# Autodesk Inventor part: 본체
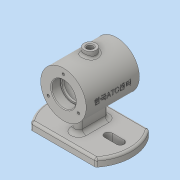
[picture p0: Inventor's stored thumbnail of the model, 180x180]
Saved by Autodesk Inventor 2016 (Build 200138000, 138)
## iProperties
Created: 2017-12
Part Number: 본체
Material: 일반
Document SubType Name: Modeling
Designer: 605-15
Density: 1 g/cm^3
Appearance: 기본값
Mass: 172.58 g
Surface Area: 486.488 cm^2
Volume: 172.58 cm^3
Author: 605-15
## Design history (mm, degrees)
sketch "스케치1"
  geometry: L1 (42.426, 35)-(-42.426, 35); L2 (42.426, -35)-(-42.426, -35); A1 r 55 centre (0, 0) between (-42.426, 35) and (-42.426, -35); A2 r 55 centre (0, 0) between (42.426, -35) and (42.426, 35); 1 further point
  constraints: 4 end point, 4 point on circle, 2 centre point, 2 horizontal, 1 coincident
  dimensions: "d1" = 70 distance between parallel lines of L2 L1; "d2" = 35 distance from line of point (0, 0) L1; "d64" = 55 radius of A2; "d65" = 55 radius of A1
extrude "돌출1" new body sketch "스케치1" distance "d3" = 10; taper "d4" = 0 deg
sketch "스케치2"
  geometry: L1 (0, 0)-(0, 62); C1 r 30 at (0, 62)
  constraints: 2 end point, 1 centre point, 1 coincident, 1 vertical
  dimensions: "d5" = 62 distance of L1.start L1.end; "d6" = 60 diameter of C1
extrude "돌출2" join sketch "스케치2" distance "d7" = 35; taper "d9" = 0 deg; dims "d8" = 35, "d10" = 0
sketch "스케치3"
  geometry: L1 (0, 15)-(0, -15); L2 (5, 15)-(5, -15); L3 (-5, -15)-(-5, 15); A1 r 5 centre (0, 15) between (5, 15) and (-5, 15); A2 r 5 centre (0, -15) between (-5, -15) and (5, -15); 1 further point
  constraints: 8 end point, 4 point on circle, 4 tangent, 2 centre point, 1 midpoint, 1 parallel, 1 vertical
  dimensions: "d11" = 5 radius of A2; "d12" = 30 distance of L1.start L1.end
extrude "돌출3" join sketch "스케치3" stored distance "d13" = 35; taper "d14" = 0 deg
node "작업 평면1"
sketch "스케치5"
  geometry: C1 r 8 at (0, 0); 1 further point
  constraints: 1 centre point, 1 coincident
  dimensions: "d24" = 16 diameter of C1
extrude "돌출4" join sketch "스케치5" distance "d25" = 37; taper "d26" = 0 deg
sketch "스케치4"
  geometry: L1 (62, 35)-(62, -35); L2 (32, -35)-(92, -35) reference; L3 (0, -35)-(0, 35) reference; L4 (92, 35)-(32, 35) reference; L5 (62, 35)-(78, 35); L6 (78, 35)-(78, 23); L7 (78, 23)-(76, 23); L8 (76, 23)-(76, 20); L9 (76, 20)-(87, 20); L10 (87, 20)-(87, -20); L11 (87, -20)-(76, -20); L12 (76, -20)-(76, -23); L13 (76, -23)-(78, -23); L14 (78, -23)-(78, -35); L15 (78, -35)-(62, -35); 1 further point
  constraints: 24 end point, 6 perpendicular, 6 point on line, 2 midpoint, 2 vertical, 1 collinear
  dimensions: "d15" = 62 distance between parallel lines of L3 L1; "d16" = 16 distance between parallel lines of L1 L6; "d17" = 14 distance between parallel lines of L1 L8; "d18" = 25 distance between parallel lines of L1 L10; "d19" = 12 distance of L5.end L6.end; "d20" = 40 distance of L9.end L10.end; "d21" = 12 distance of L13.end L14.end; "d22" = 3 distance of L7.end L8.end
revolve "회전1" sketch "스케치4" stored, may be unused: angle "d27" = 90 deg
fillet "모깎기1" dims "d28" = 3
fillet "모깎기2" dims "d29" = 0.3
chamfer "모따기1" distance "d30" = 1; stored, may be unused: second distance "d31" = 2, angle "d32" = 45 deg
sketch "스케치6"
  geometry: C1 r 4 at (0, 0); 1 further point
  constraints: 1 centre point, 1 coincident
  dimensions: "d33" = 8 diameter of C1
extrude "돌출5" cut sketch "스케치6" stored distance "d34" = 37; taper "d35" = 0 deg
chamfer "모따기2" distance "d36" = 1; stored, may be unused: second distance "d37" = 2, angle "d38" = 45 deg
sketch "스케치7"
  geometry: L1 (-24, 0)-(-40, 0); L2 (-24, -5)-(-40, -5); L3 (-40, 5)-(-24, 5); L4 (0, 0)-(-79.704, 0); L5 (0, 0)-(0, 84.273); L6 (40, 5)-(24, 5); L7 (24, -5)-(40, -5); C1 r 5 at (0, 0) reference; A1 r 5 centre (-24, 0) between (-24, -5) and (-24, 5); A2 r 5 centre (-40, 0) between (-40, 5) and (-40, -5); A3 r 5 centre (40, 0) between (40, -5) and (40, 5); A4 r 5 centre (24, 0) between (24, 5) and (24, -5); 1 further point
  constraints: 16 end point, 8 point on circle, 6 symmetric about line, 4 centre point, 4 tangent, 2 horizontal, 1 midpoint, 1 parallel, 1 point on line, 1 vertical, 2 other
  dimensions: "d39" = 16 distance of L1.start L1.end; "d40" = 5 radius of A2; "d63" = 24 distance from line of L1.start L5
extrude "돌출6" cut sketch "스케치7" stored distance "d43" = 37; taper "d44" = 0 deg
sketch "스케치8"
  geometry: L1 (0, 0)-(0, 23); 1 further point
  constraints: 2 end point, 1 vertical
  dimensions: "d45" = 23 distance of L1.start L1.end
hole "구멍1" sketch "스케치8" at (0, 23) diameter "d46" = 3.242; stored, may be unused: countersink angle "d50" = 90 deg, drill point angle "d52" = 118 deg; dims "d47" = 8, "d48" = 4, "d49" = 2, "d51" = 10
fillet "모깎기3" dims "d56" = 5
fillet "모깎기4" dims "d57" = 3
node "작업 평면2"
sketch "스케치9"
  geometry: L1 (30, 35)-(-30, 35) reference; L2 (30, -35)-(30, 35) reference; 2 further points
  constraints: 1 other
  dimensions: "d58" = 35 distance from line of point (0, 0) L1; "d59" = 30 distance from line of L2 point (0, 0)
feature "엠보싱1" sketch "스케치9" dims "d1" = 70, "d2" = 35, "d60" = 0.5, "d61" = 0, "d64" = 55, "d65" = 55
node "솔리드1"
pattern_circular "원형 패턴1" dims angle "d54" = 360 deg
mirror "대칭1"
other parameters: "d23" = 62
